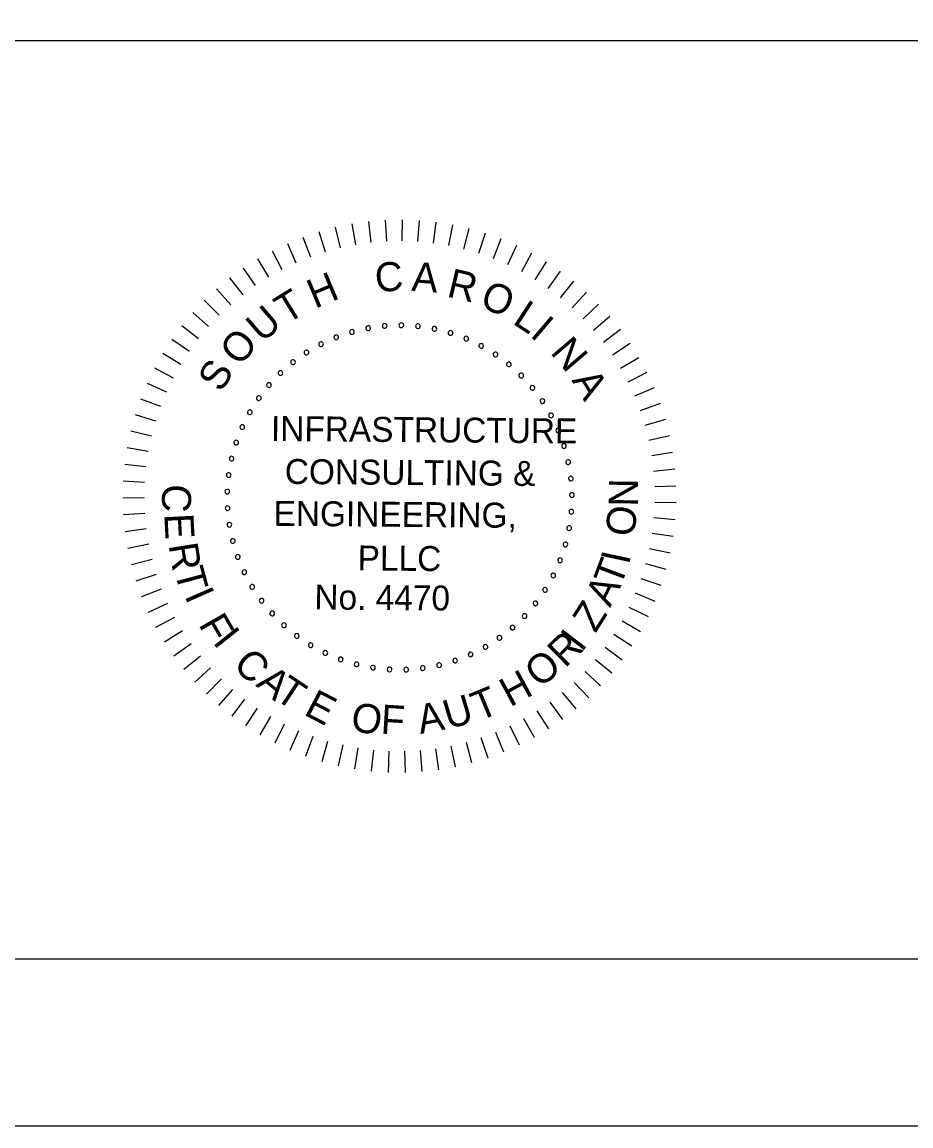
# Model space of a CAD drawing. Extents: x 1970675.2 to 1970711.3, y 796145.2 to 796167.2.
# Drawn here: x 1970700.44 to 1970703.099, y 796145.246 to 796148.551 of the extents above; entities that cross this region are included whole.
import ezdxf

# ---------------------------------------------------------------- set-up
doc = ezdxf.new("R2010")
doc.units = 0
for name, color, linetype in [('BR_BORDER LINES', 7, 'Continuous'), ('BR_TEXT', 7, 'Continuous'), ('Level 31', 7, 'Continuous')]:
    doc.layers.add(name, color=color, linetype=linetype)

msp = doc.modelspace()

# ---------------------------------------------------------------- linework, layer by layer
at = {"layer": 'BR_BORDER LINES'}
for p, q in [((1970697.8703, 796148.4964), (1970703.2355, 796148.4964)), ((1970677.0698, 796145.7463), (1970710.7358, 796145.7463))]:
    msp.add_line(p, q, dxfattribs=at)
at = {"layer": 'BR_TEXT'}
for p, q in [((1970701.4262, 796147.9473), (1970701.4372, 796147.8846)), ((1970701.4761, 796147.9545), (1970701.4834, 796147.8913)), ((1970701.5265, 796147.9587), (1970701.5298, 796147.8951)), ((1970701.5769, 796147.9597), (1970701.5764, 796147.8961)), ((1970701.6274, 796147.9577), (1970701.623, 796147.8942)), ((1970701.6776, 796147.9526), (1970701.6693, 796147.8895)), ((1970701.7274, 796147.9445), (1970701.7153, 796147.882)), ((1970701.328, 796147.9239), (1970701.3466, 796147.863)), ((1970701.3767, 796147.9371), (1970701.3916, 796147.8752)), ((1970701.7767, 796147.9333), (1970701.7608, 796147.8717)), ((1970701.8251, 796147.9192), (1970701.8055, 796147.8586)), ((1970701.2334, 796147.8887), (1970701.2593, 796147.8305)), ((1970701.2802, 796147.9077), (1970701.3025, 796147.8481)), ((1970701.8726, 796147.9021), (1970701.8494, 796147.8428)), ((1970701.919, 796147.8822), (1970701.8922, 796147.8244)), ((1970701.1879, 796147.8668), (1970701.2173, 796147.8103)), ((1970701.9641, 796147.8594), (1970701.9338, 796147.8034)), ((1970701.1014, 796147.8149), (1970701.1374, 796147.7625)), ((1970701.1439, 796147.8422), (1970701.1766, 796147.7876)), ((1970702.0077, 796147.834), (1970701.974, 796147.78)), ((1970701.0606, 796147.7852), (1970701.0998, 796147.735)), ((1970702.0497, 796147.8059), (1970702.0128, 796147.7541)), ((1970701.0217, 796147.7529), (1970701.0639, 796147.7052)), ((1970702.0899, 796147.7754), (1970702.0499, 796147.7259)), ((1970700.9849, 796147.7184), (1970701.0299, 796147.6734)), ((1970702.1281, 796147.7424), (1970702.0852, 796147.6954)), ((1970700.9502, 796147.6817), (1970700.9979, 796147.6395)), ((1970702.1643, 796147.7072), (1970702.1186, 796147.6629)), ((1970702.1982, 796147.6699), (1970702.1499, 796147.6284)), ((1970700.9179, 796147.643), (1970700.968, 796147.6037)), ((1970702.2299, 796147.6305), (1970702.1791, 796147.5921)), ((1970700.8879, 796147.6023), (1970700.9404, 796147.5662)), ((1970702.259, 796147.5893), (1970702.206, 796147.5541)), ((1970700.8605, 796147.5599), (1970700.9151, 796147.5271)), ((1970700.8358, 796147.5159), (1970700.8922, 796147.4865)), ((1970702.2856, 796147.5464), (1970702.2305, 796147.5145)), ((1970702.3095, 796147.5019), (1970702.2526, 796147.4734)), ((1970700.8137, 796147.4705), (1970700.8719, 796147.4445)), ((1970702.3307, 796147.4561), (1970702.2722, 796147.4311)), ((1970700.7945, 796147.4238), (1970700.8541, 796147.4014)), ((1970702.3491, 796147.4091), (1970702.2891, 796147.3877)), ((1970700.7782, 796147.3761), (1970700.839, 796147.3574)), ((1970702.3645, 796147.361), (1970702.3033, 796147.3433)), ((1970700.7648, 796147.3274), (1970700.8267, 796147.3124)), ((1970702.377, 796147.3121), (1970702.3148, 796147.2982)), ((1970700.7543, 796147.278), (1970700.817, 796147.2668)), ((1970702.3864, 796147.2625), (1970702.3236, 796147.2524)), ((1970700.747, 796147.228), (1970700.8102, 796147.2207)), ((1970702.3929, 796147.2124), (1970702.3295, 796147.2062)), ((1970700.7426, 796147.1777), (1970700.8062, 796147.1743)), ((1970702.3963, 796147.1621), (1970702.3326, 796147.1597)), ((1970700.7414, 796147.1273), (1970700.8051, 796147.1277)), ((1970702.3965, 796147.1116), (1970702.3329, 796147.1131)), ((1970700.7432, 796147.0768), (1970700.8067, 796147.0812)), ((1970702.3938, 796147.0612), (1970702.3303, 796147.0666)), ((1970700.7481, 796147.0266), (1970700.8113, 796147.0348)), ((1970702.3879, 796147.011), (1970702.3249, 796147.0203)), ((1970700.7561, 796146.9767), (1970700.8186, 796146.9888)), ((1970702.379, 796146.9613), (1970702.3167, 796146.9744)), ((1970700.7671, 796146.9275), (1970700.8287, 796146.9433)), ((1970702.3671, 796146.9123), (1970702.3057, 796146.9291)), ((1970700.781, 796146.8789), (1970700.8416, 796146.8985)), ((1970700.7979, 796146.8314), (1970700.8572, 796146.8546)), ((1970702.3522, 796146.864), (1970702.2919, 796146.8846)), ((1970702.3344, 796146.8168), (1970702.2755, 796146.841)), ((1970700.8177, 796146.7849), (1970700.8755, 796146.8117)), ((1970702.3138, 796146.7707), (1970702.2564, 796146.7985)), ((1970700.8403, 796146.7397), (1970700.8963, 796146.77)), ((1970702.2904, 796146.726), (1970702.2348, 796146.7572)), ((1970700.8655, 796146.696), (1970700.9196, 796146.7297)), ((1970700.8934, 796146.654), (1970700.9453, 796146.6908)), ((1970702.2643, 796146.6828), (1970702.2107, 796146.7173)), ((1970702.2356, 796146.6412), (1970702.1843, 796146.6789)), ((1970700.9238, 796146.6137), (1970700.9734, 796146.6536)), ((1970702.2044, 796146.6015), (1970702.1555, 796146.6423)), ((1970700.9566, 796146.5753), (1970701.0037, 796146.6182)), ((1970702.1709, 796146.5638), (1970702.1245, 796146.6074)), ((1970700.9917, 796146.539), (1970701.0361, 796146.5847)), ((1970702.1351, 796146.5281), (1970702.0915, 796146.5745)), ((1970701.0289, 796146.5049), (1970701.0704, 796146.5532)), ((1970701.0682, 796146.4731), (1970701.1066, 796146.5239)), ((1970702.0973, 796146.4948), (1970702.0566, 796146.5437)), ((1970701.1093, 796146.4438), (1970701.1446, 796146.4968)), ((1970702.0574, 796146.4637), (1970702.0198, 796146.5151)), ((1970701.1521, 796146.4171), (1970701.1841, 796146.4721)), ((1970701.9725, 796146.4093), (1970701.9414, 796146.4648)), ((1970702.0158, 796146.4352), (1970701.9813, 796146.4888)), ((1970701.1965, 796146.393), (1970701.225, 796146.4499)), ((1970701.2422, 796146.3716), (1970701.2673, 796146.4302)), ((1970701.8815, 796146.3656), (1970701.8574, 796146.4245)), ((1970701.9276, 796146.386), (1970701.9, 796146.4434)), ((1970701.2892, 796146.3531), (1970701.3106, 796146.4131)), ((1970701.3372, 796146.3375), (1970701.3549, 796146.3986)), ((1970701.7859, 796146.3332), (1970701.7691, 796146.3947)), ((1970701.8342, 796146.3479), (1970701.8137, 796146.4082)), ((1970701.386, 796146.3248), (1970701.4001, 796146.3869)), ((1970701.4356, 796146.3152), (1970701.4458, 796146.378)), ((1970701.4856, 796146.3086), (1970701.492, 796146.3719)), ((1970701.536, 796146.305), (1970701.5385, 796146.3686)), ((1970701.5865, 796146.3045), (1970701.5851, 796146.3682)), ((1970701.6369, 796146.3071), (1970701.6316, 796146.3706)), ((1970701.6871, 796146.3128), (1970701.6779, 796146.3758)), ((1970701.7368, 796146.3215), (1970701.7238, 796146.3838))]:
    msp.add_line(p, q, dxfattribs=at)
for centre, start, end in [((1970701.5247, 796147.6417), 5.0653, 185.0653), ((1970701.5745, 796147.6436), 359.5268, 179.5268), ((1970701.6242, 796147.6407), 353.9884, 173.9884), ((1970701.3797, 796147.6075), 21.6807, 201.6807), ((1970701.4268, 796147.6235), 16.1422, 196.1422), ((1970701.4268, 796147.6235), 196.1422, 16.1422), ((1970701.4753, 796147.635), 10.6038, 190.6038), ((1970701.4753, 796147.635), 190.6038, 10.6038), ((1970701.5247, 796147.6417), 185.0653, 5.0653), ((1970701.5745, 796147.6436), 179.5268, 359.5268), ((1970701.6242, 796147.6407), 173.9884, 353.9884), ((1970701.6735, 796147.6329), 168.4499, 348.4499), ((1970701.6735, 796147.6329), 348.4499, 168.4499), ((1970701.7217, 796147.6205), 162.9114, 342.9114), ((1970701.7217, 796147.6205), 342.9114, 162.9114), ((1970701.3343, 796147.587), 27.2191, 207.2191), ((1970701.3343, 796147.587), 207.2191, 27.2191), ((1970701.3797, 796147.6075), 201.6807, 21.6807), ((1970701.7686, 796147.6035), 157.373, 337.373), ((1970701.7686, 796147.6035), 337.373, 157.373), ((1970701.8135, 796147.582), 151.8345, 331.8345), ((1970701.8135, 796147.582), 331.8345, 151.8345), ((1970701.291, 796147.5621), 32.7576, 212.7576), ((1970701.291, 796147.5621), 212.7576, 32.7576), ((1970701.8562, 796147.5563), 146.2961, 326.2961), ((1970701.8562, 796147.5563), 326.2961, 146.2961), ((1970701.2504, 796147.5333), 38.2961, 218.2961), ((1970701.2504, 796147.5333), 218.2961, 38.2961), ((1970701.8962, 796147.5266), 140.7576, 320.7576), ((1970701.8962, 796147.5266), 320.7576, 140.7576), ((1970701.2128, 796147.5006), 43.8345, 223.8345), ((1970701.2128, 796147.5006), 223.8345, 43.8345), ((1970701.9332, 796147.4932), 135.2191, 315.2191), ((1970701.9332, 796147.4932), 315.2191, 135.2191), ((1970701.1785, 796147.4645), 49.373, 229.373), ((1970701.1785, 796147.4645), 229.373, 49.373), ((1970701.9668, 796147.4564), 129.6807, 309.6807), ((1970701.9668, 796147.4564), 309.6807, 129.6807), ((1970701.1478, 796147.4252), 54.9114, 234.9114), ((1970701.1478, 796147.4252), 234.9114, 54.9114), ((1970701.9966, 796147.4165), 124.1422, 304.1422), ((1970701.9966, 796147.4165), 304.1422, 124.1422), ((1970701.1211, 796147.3831), 60.4499, 240.4499), ((1970701.1211, 796147.3831), 240.4499, 60.4499), ((1970702.0225, 796147.3739), 118.6038, 298.6038), ((1970702.0225, 796147.3739), 298.6038, 118.6038), ((1970701.0986, 796147.3387), 65.9884, 245.9884), ((1970701.0986, 796147.3387), 245.9884, 65.9884), ((1970702.0441, 796147.329), 113.0653, 293.0653), ((1970702.0441, 796147.329), 293.0653, 113.0653), ((1970701.0804, 796147.2923), 71.5268, 251.5268), ((1970701.0804, 796147.2923), 251.5268, 71.5268), ((1970702.0613, 796147.2822), 107.5268, 287.5268), ((1970702.0613, 796147.2822), 287.5268, 107.5268), ((1970701.0668, 796147.2443), 77.0653, 257.0653), ((1970701.0668, 796147.2443), 257.0653, 77.0653), ((1970702.0739, 796147.234), 101.9884, 281.9884), ((1970702.0739, 796147.234), 281.9884, 101.9884), ((1970701.0579, 796147.1953), 82.6038, 262.6038), ((1970701.0579, 796147.1953), 262.6038, 82.6038), ((1970702.0818, 796147.1848), 96.4499, 276.4499), ((1970702.0818, 796147.1848), 276.4499, 96.4499), ((1970701.0538, 796147.1456), 88.1422, 268.1422), ((1970701.0538, 796147.1456), 268.1422, 88.1422), ((1970702.0849, 796147.1351), 90.9114, 270.9114), ((1970702.0849, 796147.1351), 270.9114, 90.9114), ((1970701.0545, 796147.0958), 93.6807, 273.6807), ((1970701.0545, 796147.0958), 273.6807, 93.6807), ((1970702.0832, 796147.0853), 85.373, 265.373), ((1970702.0832, 796147.0853), 265.373, 85.373), ((1970701.06, 796147.0463), 99.2191, 279.2191), ((1970701.06, 796147.0463), 279.2191, 99.2191), ((1970702.0766, 796147.0359), 79.8345, 259.8345), ((1970702.0766, 796147.0359), 259.8345, 79.8345), ((1970701.0703, 796146.9975), 104.7576, 284.7576), ((1970701.0703, 796146.9975), 284.7576, 104.7576), ((1970702.0654, 796146.9873), 74.2961, 254.2961), ((1970702.0654, 796146.9873), 254.2961, 74.2961), ((1970701.0852, 796146.95), 110.2961, 290.2961), ((1970701.0852, 796146.95), 290.2961, 110.2961), ((1970702.0495, 796146.9401), 68.7576, 248.7576), ((1970702.0495, 796146.9401), 248.7576, 68.7576), ((1970701.1046, 796146.9041), 115.8345, 295.8345), ((1970701.1046, 796146.9041), 295.8345, 115.8345), ((1970702.0291, 796146.8946), 63.2191, 243.2191), ((1970702.0291, 796146.8946), 243.2191, 63.2191), ((1970701.1284, 796146.8603), 121.373, 301.373), ((1970701.1284, 796146.8603), 301.373, 121.373), ((1970702.0045, 796146.8513), 57.6807, 237.6807), ((1970702.0045, 796146.8513), 237.6807, 57.6807), ((1970701.1563, 796146.819), 126.9114, 306.9114), ((1970701.1563, 796146.819), 306.9114, 126.9114), ((1970701.188, 796146.7806), 312.4499, 132.4499), ((1970701.9758, 796146.8106), 52.1422, 232.1422), ((1970701.9758, 796146.8106), 232.1422, 52.1422), ((1970701.188, 796146.7806), 132.4499, 312.4499), ((1970701.9432, 796146.7728), 46.6038, 226.6038), ((1970701.9432, 796146.7728), 226.6038, 46.6038), ((1970701.2233, 796146.7454), 137.9884, 317.9884), ((1970701.2233, 796146.7454), 317.9884, 137.9884), ((1970701.9072, 796146.7384), 41.0653, 221.0653), ((1970701.9072, 796146.7384), 221.0653, 41.0653), ((1970701.2618, 796146.7138), 143.5268, 323.5268), ((1970701.2618, 796146.7138), 323.5268, 143.5268), ((1970701.3032, 796146.6861), 149.0653, 329.0653), ((1970701.3032, 796146.6861), 329.0653, 149.0653), ((1970701.8681, 796146.7076), 35.5268, 215.5268), ((1970701.8681, 796146.7076), 215.5268, 35.5268), ((1970701.3471, 796146.6625), 154.6038, 334.6038), ((1970701.3471, 796146.6625), 334.6038, 154.6038), ((1970701.7817, 796146.658), 24.4499, 204.4499), ((1970701.7817, 796146.658), 204.4499, 24.4499), ((1970701.8261, 796146.6807), 29.9884, 209.9884), ((1970701.8261, 796146.6807), 209.9884, 29.9884), ((1970701.3931, 796146.6432), 160.1422, 340.1422), ((1970701.3931, 796146.6432), 340.1422, 160.1422), ((1970701.4407, 796146.6285), 165.6807, 345.6807), ((1970701.4407, 796146.6285), 345.6807, 165.6807), ((1970701.4895, 796146.6184), 351.2191, 171.2191), ((1970701.6385, 796146.6169), 7.8345, 187.8345), ((1970701.6875, 796146.6259), 13.373, 193.373), ((1970701.6875, 796146.6259), 193.373, 13.373), ((1970701.7354, 796146.6397), 18.9114, 198.9114), ((1970701.7354, 796146.6397), 198.9114, 18.9114), ((1970701.4895, 796146.6184), 171.2191, 351.2191), ((1970701.539, 796146.6131), 356.7576, 176.7576), ((1970701.539, 796146.6131), 176.7576, 356.7576), ((1970701.5889, 796146.6126), 2.2961, 182.2961), ((1970701.5889, 796146.6126), 182.2961, 2.2961), ((1970701.6385, 796146.6169), 187.8345, 7.8345)]:
    msp.add_arc(centre, 0.00701, start, end, dxfattribs=at)
at = {"layer": 'Level 31'}
msp.add_lwpolyline([(1970675.2365, 796167.2463), (1970675.2365, 796145.2464), (1970711.2364, 796145.2464), (1970711.2364, 796167.2463)], dxfattribs=at)

# ---------------------------------------------------------------- texts
at = {"layer": 'BR_TEXT'}
for s, height, rotation, p in [('C', 0.0872, 4.7281, (1970701.499, 796147.7421)), ('A', 0.0872, 355.6981, (1970701.6035, 796147.7471)), ('R', 0.0872, 346.6681, (1970701.7077, 796147.7301)), ('H', 0.0872, 22.7882, (1970701.3162, 796147.6927)), ('T', 0.0872, 31.8182, (1970701.2313, 796147.6451)), ('O', 0.0872, 337.638, (1970701.8055, 796147.7003)), ('L', 0.0872, 327.108, (1970701.9043, 796147.6498)), ('U', 0.0872, 40.8482, (1970701.158, 796147.589)), ('I', 0.0872, 319.578, (1970701.9569, 796147.612)), ('O', 0.0872, 49.8782, (1970701.091, 796147.518)), ('N', 0.0872, 310.548, (1970702.0177, 796147.5612)), ('S', 0.0872, 58.9083, (1970701.0356, 796147.4398)), ('A', 0.0872, 301.5179, (1970702.0828, 796147.4788)), ('INFRASTRUCTURE', 0.074771, 359.5268, (1970701.1842, 796147.2972)), ('CONSULTING &', 0.074771, 359.5268, (1970701.2255, 796147.1686)), ('C', 0.0872, 267.025, (1970700.8606, 796147.1698)), ('N', 0.0872, 89.2085, (1970702.2821, 796147.1001)), ('ENGINEERING,', 0.074771, 359.5268, (1970701.1919, 796147.0432)), ('O', 0.0872, 83.2085, (1970702.271, 796147.0086)), ('E', 0.0872, 273.025, (1970700.865, 796147.0783)), ('R', 0.0872, 279.025, (1970700.8778, 796146.986)), ('PLLC', 0.07477, 359.5268, (1970701.4436, 796146.9096)), ('I', 0.0872, 77.9093, (1970702.2555, 796146.9243)), ('T', 0.0872, 285.025, (1970700.8952, 796146.9072)), ('T', 0.0872, 69.3954, (1970702.2298, 796146.8568)), ('I', 0.0872, 293.7713, (1970700.9249, 796146.8341)), ('No. 4470', 0.07477, 359.5268, (1970701.3141, 796146.7927)), ('A', 0.0872, 63.3954, (1970702.199, 796146.7965)), ('Z', 0.0872, 57.3954, (1970702.1551, 796146.7202)), ('F', 0.0872, 299.7713, (1970700.9661, 796146.748)), ('I', 0.0872, 308.5268, (1970701.0082, 796146.6942)), ('I', 0.0872, 52.3339, (1970702.1141, 796146.6625)), ('R', 0.0872, 44.5268, (1970702.0647, 796146.6152)), ('C', 0.0872, 314.5268, (1970701.0675, 796146.6241)), ('O', 0.0872, 38.5268, (1970701.9881, 796146.5552)), ('A', 0.0872, 320.5268, (1970701.1367, 796146.5655)), ('T', 0.0872, 326.5268, (1970701.1911, 796146.527)), ('H', 0.0872, 28.5268, (1970701.9, 796146.4992)), ('T', 0.0872, 22.5268, (1970701.8068, 796146.4575)), ('E', 0.0872, 332.5268, (1970701.2797, 796146.4792)), ('U', 0.0872, 16.5268, (1970701.7151, 796146.4331)), ('O', 0.0872, 350.5268, (1970701.4198, 796146.4304)), ('F', 0.0872, 356.5268, (1970701.5113, 796146.4212)), ('A', 0.0872, 10.5268, (1970701.6312, 796146.4196))]:
    msp.add_text(s, height=height, rotation=rotation, dxfattribs=at).set_placement(p)

doc.saveas('drawing.dxf')
